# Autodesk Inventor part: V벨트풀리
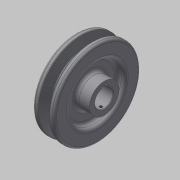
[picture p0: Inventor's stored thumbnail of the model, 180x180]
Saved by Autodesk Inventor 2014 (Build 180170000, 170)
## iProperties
Created: 2015-11
Part Number: V벨트풀리
Material: 강철, 탄소
Document SubType Name: Modeling
Designer: mduedu
Density: 1 g/cm^3
Appearance: Default
Author: mduedu
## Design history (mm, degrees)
sketch "스케치1"
  geometry: L1 (-9.5, 0)-(9.5, 0); L2 (0, 0)-(0, 37.7); L3 (-4.825, 37.7)-(-9.5, 37.7); L4 (-9.5, 37.7)-(-9.5, 0); L5 (0, 28.7)-(-2.074, 28.7); L6 (-2.074, 28.7)-(-4.825, 37.7); L7 (4.825, 37.7)-(9.5, 37.7); L8 (9.5, 37.7)-(9.5, 0); L9 (0, 28.7)-(2.074, 28.7); L10 (2.074, 28.7)-(4.825, 37.7); L11 (-9.5, 35)-(9.5, 35); 3 further points
  constraints: 22 end point, 7 point on line, 4 perpendicular, 3 symmetric about line, 1 coincident, 1 horizontal, 1 horizontal alignment, 1 midpoint, 1 vertical
  dimensions: "d0" = 19 distance of L1.start L1.end; "d2" = 75.4 diameter of L2.end L1 (derived); "d3" = 34 deg angle of L10 L6; "d4" = 6.3 distance between parallel lines of L11 L9; "d5" = 2.7 distance between parallel lines of L7 L11; "d6" = 8 distance of point (4, 35) point (-4, 35); "d7" = 70 diameter of L11 L1
revolve "회전1" sketch "스케치1" stored, may be unused: angle "d8" = 90 deg
sketch "스케치2"
  geometry: C1 r 24 at (0, 0); C2 r 13 at (0, 0); 1 further point
  constraints: 2 centre point, 2 coincident
  dimensions: "d9" = 48 diameter of C1; "d10" = 26 diameter of C2
extrude "돌출1" cut sketch "스케치2" distance "d11" = 6; taper "d12" = 0 deg
extrude "돌출3" join sketch "스케치2" distance "d37" = 6; taper "d38" = 0 deg
fillet "모깎기1" dims "d13" = 3
fillet "모깎기2" dims "d14" = 3
fillet "모깎기3" dims "d15" = 1, "d16" = 0.5, "d17" = 2
hole "구멍1" diameter "d20" = 16; stored, may be unused: countersink angle "d24" = 90 deg, drill point angle "d26" = 118 deg; dims "d21" = 6, "d22" = 4, "d23" = 2, "d25" = 8, "d53" = 10, "d54" = 10
sketch "스케치3"
  geometry: L1 (-2.5, 0)-(2.5, 0); L2 (2.5, 0)-(2.5, 10.3); L3 (2.5, 10.3)-(-2.5, 10.3); L4 (-2.5, 10.3)-(-2.5, 0); 2 further points
  constraints: 8 end point, 2 parallel, 1 coincident, 1 horizontal, 1 midpoint, 1 perpendicular
  dimensions: "d27" = 5 distance of L2.end L3.end; "d29" = 10.3 distance of L3.end L1.start
extrude "돌출2" cut sketch "스케치3" stored distance "d30" = 6; taper "d31" = 0 deg
node "작업 평면1"
sketch "스케치4"
  geometry: L1 (19, -27)-(19, 27) reference; 2 further points
  constraints: 1 horizontal alignment
  dimensions: "d52" = 22 distance from line of L1 point (-3, 0)
hole "구멍2" sketch "스케치4" at (-3, 0) diameter "d42" = 2.459; stored, may be unused: countersink angle "d46" = 90 deg, drill point angle "d48" = 118 deg; dims "d43" = 6, "d44" = 4, "d45" = 2, "d47" = 8
chamfer "모따기3" distance "d58" = 0.5; stored, may be unused: second distance "d59" = 2, angle "d60" = 45 deg
node "솔리드1"
mirror "대칭1"
